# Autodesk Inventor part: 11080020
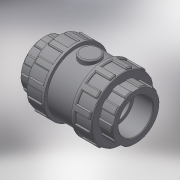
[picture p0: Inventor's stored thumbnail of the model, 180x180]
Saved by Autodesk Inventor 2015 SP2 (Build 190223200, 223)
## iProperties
Created: 2017-11
Part Number: 11080020
Material: Generic
Description: PLASSON CHECK VALVE CEM 20 PTFE COATED SPRING + EPDM O-RING
Document SubType Name: Modeling
Designer: KIM
Density: 1 g/cm^3
Appearance: Default
Author: KIM
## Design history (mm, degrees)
derived "110800 - 110600 110900-110000.ipt"
feature "Solid1::110800 - 110600 110900-110000.ipt"
tag "TaggingFeature1"
body "Solid1"
other parameters: "d0" = 75, "d2" = 45, "d3" = 16, "d4" = 16, "d5" = 11.2, "d7" = 28, "d8" = 40.5, "d13" = 0.6, "d23" = 16, "d24" = 43.2, "d25" = 0.4, "d26" = 0.6, "d27" = 6.75, "d28" = 3.375, "d29" = 12, "d30" = 0, "d35" = 0.6, "d39" = 22.5, "d45" = 360 deg, "d47" = 0.4, "d50" = 22.5, "d51" = 13.5, "d53" = 0, "d54" = 0.9, "d55" = 4, "d56" = 2, "d57" = 11.2, "d58" = 0, "d59" = 0.6, "d61" = 360 deg, "l_" = 16, "H_" = 75, "K_" = 45
